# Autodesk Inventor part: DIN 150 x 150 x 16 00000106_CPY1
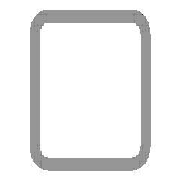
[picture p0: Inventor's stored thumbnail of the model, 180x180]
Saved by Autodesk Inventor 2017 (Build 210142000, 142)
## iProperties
Created: 2017-11
Part Number: DIN 150 x 150 x 16 00000106_CPY1
Material: Steel, Mild
Description: Cold formed welded structural hollow sections of non-alloy and fine grain structural steel
Document SubType Name: Modeling
Standard: DIN
Designer: iusti
Standard Revision: 2006-07
Standards Organization: DIN
Language: en-US
Size Designation: 150 x 150 x 16
Categories: <MemberInstance><Categories><Category DisplayName="Structural Shapes" InternalName="089c4875-fa83-4c05-b084-43b9cc11f5ed" Mnemonic="GRDR"><CategoryParameter Dis
Stock Number: 150 x 150 x 16
Mass: 88044.5 g
Surface Area: 14205.2 cm^2
Volume: 11215.9 cm^3
Density: 7.85 g/cm^3
Appearance: Semi-Polished
IsCustomPart: 1
G_W: 150.000 mm
G_H: 150.000 mm
G_L: 1602.478 mm
+346FD258-9F9C-4BDE-884E-4FE9BE76FCEA+CUTDETAIL2: Miter 69.88 deg
+B95BDB02-C4C2-4ECB-9363-19BA39C44CCB+CUTDETAIL3: Miter 45.00 deg
_CCFamilyMember: 76
_CCFamilyDisplayName: DIN EN 10219-2 (Square Hollow Section - Cold Formed) - Cold formed welded structural hollow sections of non-alloy and fine grain structural steel
_FrameMemberDoc: Frame Member File
_Version: 15.0.0
_GetPNFromCC: 1
Author: iusti
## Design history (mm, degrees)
node "Start plane"
node "End plane"
sketch "Sketch"
  geometry: L1 (-75, -27)-(-75, 27); L2 (-27, 75)-(27, 75); L3 (75, 27)-(75, -27); L4 (27, -75)-(-27, -75); L5 (-27, 59)-(27, 59); L6 (59, 27)-(59, -27); L7 (27, -59)-(-27, -59); L8 (-59, -27)-(-59, 27); L9 (0, 118.918)-(0, -118.918) reference; L10 (-118.918, 0)-(118.918, 0) reference; A1 r 48 centre (-27, -27) between (-75, -27) and (-27, -75); A2 r 48 centre (-27, 27) between (-27, 75) and (-75, 27); A3 r 48 centre (27, 27) between (75, 27) and (27, 75); A4 r 48 centre (27, -27) between (27, -75) and (75, -27); A5 r 32 centre (-27, 27) between (-27, 59) and (-59, 27); A6 r 32 centre (27, 27) between (59, 27) and (27, 59); A7 r 32 centre (27, -27) between (27, -59) and (59, -27); A8 r 32 centre (-27, -27) between (-59, -27) and (-27, -59)
  constraints: 16 end point, 16 point on circle, 8 centre point, 8 tangent, 4 parallel, 3 equal radius, 2 perpendicular, 7 other
  dimensions: "d7" = 48 radius of A1 (= G_IR); "d10" = 150 distance between parallel lines of L2 L4 (= G_H); "d11" = 150 distance between parallel lines of L1 L3 (= G_W); "d12" = 16 distance between parallel lines of L3 L6 (= G_T); "d15" = 75 distance between parallel lines of L2 L10 (= 0.5 x d10); "d16" = 75 distance between parallel lines of L9 L3 (= 0.5 x d11)
extrude "Body" new body sketch "Sketch" stored distance "d3" = 1602.4779 (= G_L); taper "d4" = 0 deg
node "Driven Length"
  sketch "Sketch3"
    geometry: L1 (0, 0)-(10, 0) reference
    constraints: 2 end point, 1 horizontal
  workplane "Work Plane3"
  sketch "Sketch4"
    geometry: L1 (-2, -75)-(12, -75) reference; L2 (-2, 1527.478)-(12, 1527.478) reference
    dimensions: "d18" = 1602.4779 distance between parallel lines of L1 L2 (derived)
workplane "Work Plane5"
split "Split2"
workplane "Work Plane6"
split "Split3"
body "Solid1"
other parameters: "G_W" = 150 [user parameter; used in 1 equation term], "G_H" = 150 [user parameter; used in 1 equation term], "G_T" = 16 [user parameter; used in 1 equation term], "G_IR" = 48 [user parameter; used in 1 equation term], "G_L" = 1602.4779 (= d18) [user parameter; used in 1 equation term], "G_OFFSET_START" = 75 [user parameter; used in 1 equation term], "G_OFFSET_END" = 27.4779 [user parameter; used in 1 equation term], "d13" = -75 (= -G_OFFSET_START), "d14" = 1527.4779 (= G_OFFSET_END + B_L), "d17" = 90 deg
